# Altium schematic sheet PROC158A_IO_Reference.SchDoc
size A2; Date: Not shown in title block; ApprovedBy: Not shown in title block; CheckedBy: Not shown in title block; Author: Not shown in title block; CompanyName: Not shown in title block; Engineer: Not shown in title block; Organization: Not shown in title block; Address1: Not shown in title block; Address2: Not shown in title block; Address3: Not shown in title block; Address4: Not shown in title block; DocumentNumber: 2; Revision: Use project parameter SCH_Rev; SheetNumber: 2; SheetTotal: 24; PageSetup: Record=PageOptions¦CenterHorizontal=True¦CenterVertical=True¦PrintScale=1.00¦XCorrection=1.00¦YCorrection=1.00¦PrintKind=0¦BorderSize=5000000¦LeftOffset=0¦BottomOffset=0¦Orientation=2¦PaperLength=1000¦PaperWidth=1000¦Scale=100¦PaperSource=15¦PrintQuality=600¦MediaType=1¦DitherType=10¦PaperKind=Letter¦PrintScaleMode=1
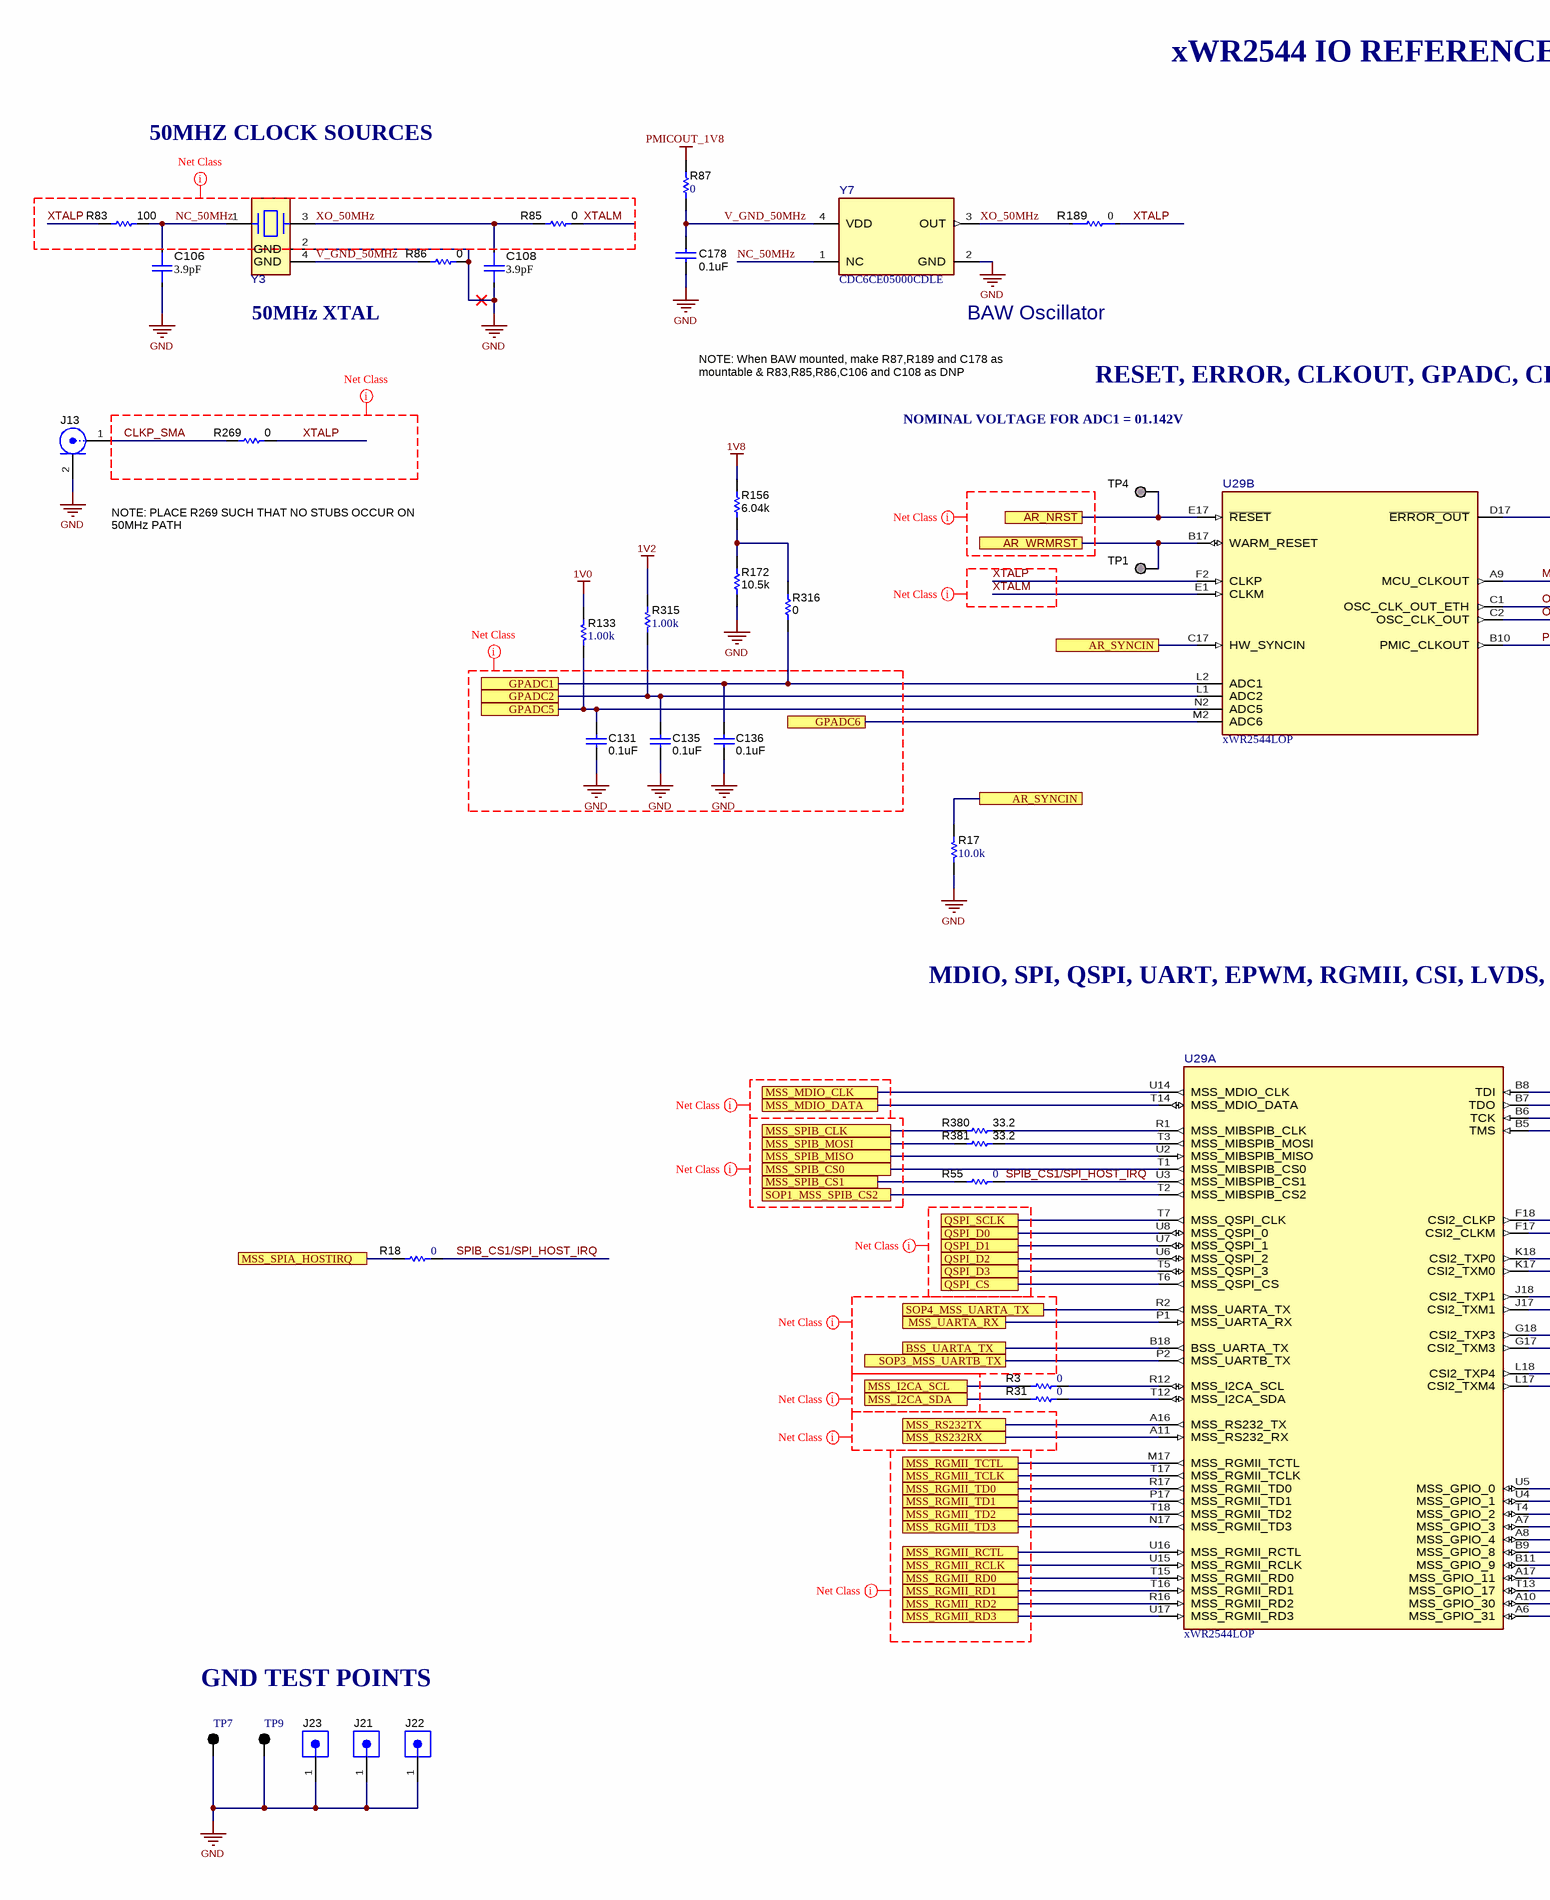
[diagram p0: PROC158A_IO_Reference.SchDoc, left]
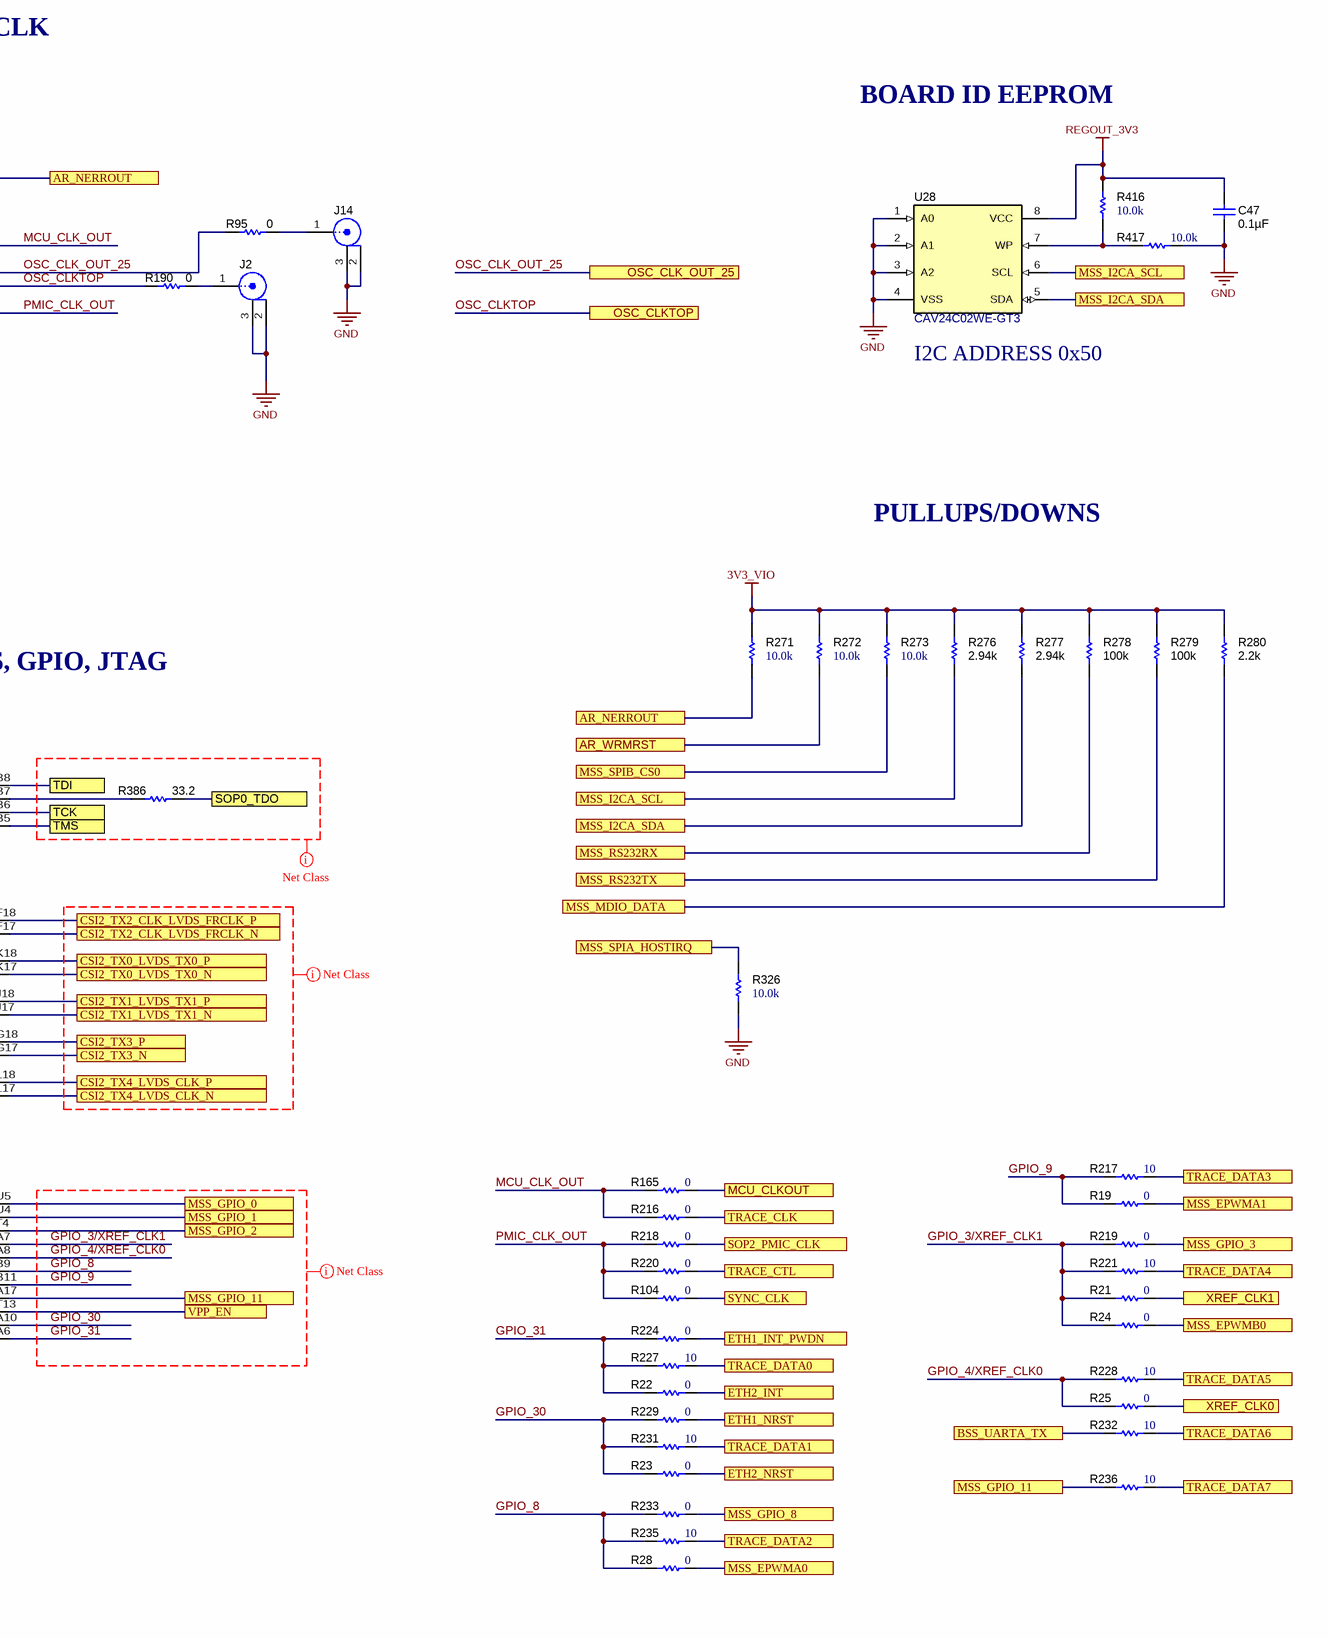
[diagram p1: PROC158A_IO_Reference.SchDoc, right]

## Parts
C47  ValueDisplayed: 0.1µF  [0402L]  (hidden comment: C0402C104K8RACTU)
C106  ValueDisplayed: 3.9pF  [FP-GCM1555C1H3R9BA16D_0402-MFG]  (hidden comment: GCM1555C1H3R9BA16D)
C108  ValueDisplayed: 3.9pF  [FP-GCM1555C1H3R9BA16D_0402-MFG]  (hidden comment: GCM1555C1H3R9BA16D)
C131  ValueDisplayed: 0.1uF  [0402L]  (hidden comment: GCM155R71C104KA55D)
C135  ValueDisplayed: 0.1uF  [0402L]  (hidden comment: GCM155R71C104KA55D)
C136  ValueDisplayed: 0.1uF  [0402L]  (hidden comment: GCM155R71C104KA55D)
C178  ValueDisplayed: 0.1uF  [0402L]  (hidden comment: GCM155R71C104KA55D)
J2  128-0711-201  [Johnson_128-0711-201]  (value not drawn)
J13  142-0711-201  [142-0711-201]  (value not drawn)
J14  128-0711-201  [Johnson_128-0711-201]  (value not drawn)
J21  GBC01SFBN-M30  [Sullins_GBC01SFBN-M30]  (value not drawn)
J22  GBC01SFBN-M30  [Sullins_GBC01SFBN-M30]  (value not drawn)
J23  GBC01SFBN-M30  [Sullins_GBC01SFBN-M30]  (value not drawn)
R3  ValueDisplayed: 0  [0402L]  (hidden comment: ERJ-2GE0R00X)
R17  ValueDisplayed: 10.0k  [0402L]  (hidden comment: CRCW040210K0FKED)
R18  ValueDisplayed: 0  [0201L]  (hidden comment: CRCW02010000Z0ED)
R19  value 0  [0402L]  (hidden comment: ERJ-2GE0R00X)
R21  ValueDisplayed: 0  [0201L]  (hidden comment: CRCW02010000Z0ED)
R22  ValueDisplayed: 0  [0402L]  (hidden comment: ERJ-2GE0R00X)
R23  ValueDisplayed: 0  [0402L]  (hidden comment: ERJ-2GE0R00X)
R24  ValueDisplayed: 0  [0201L]  (hidden comment: CRCW02010000Z0ED)
R25  ValueDisplayed: 0  [0201L]  (hidden comment: CRCW02010000Z0ED)
R28  value 0  [0402L]  (hidden comment: ERJ-2GE0R00X)
R31  ValueDisplayed: 0  [0402L]  (hidden comment: ERJ-2GE0R00X)
R55  ValueDisplayed: 0  [0402L]  (hidden comment: ERJ-2GE0R00X)
R83  ValueDisplayed: 100  [0402L]  (hidden comment: ERJ-2GEJ101X)
R85  ValueDisplayed: 0  [0402L]  (hidden comment: ERJ-2GE0R00X)
R86  ValueDisplayed: 0  [0402L]  (hidden comment: ERJ-2GE0R00X)
R87  ValueDisplayed: 0  [0402L]  (hidden comment: ERJ-2GE0R00X)
R95  ValueDisplayed: 0  [0402L]  (hidden comment: ERJ-2GE0R00X)
R104  ValueDisplayed: 0  [0201L]  (hidden comment: CRCW02010000Z0ED)
R133  ValueDisplayed: 1.00k  [0402L]  (hidden comment: CRCW04021K00FKED)
R156  ValueDisplayed: 6.04k  [0402L]  (hidden comment: CRCW04026K04FKED)
R165  ValueDisplayed: 0  [0201L]  (hidden comment: CRCW02010000Z0ED)
R172  ValueDisplayed: 10.5k  [0402L]  (hidden comment: CRCW040210K5FKED)
R189  Res_ohm: 0  [FP-HCJ0603ZT0R00_0603-MFG]  (hidden comment: HCJ0603ZT0R00)
R190  ValueDisplayed: 0  [0402L]  (hidden comment: ERJ-2GE0R00X)
R216  ValueDisplayed: 0  [0201L]  (hidden comment: CRCW02010000Z0ED)
R217  ValueDisplayed: 10  [0201L]  (hidden comment: RC0201JR-0710RL)
R218  ValueDisplayed: 0  [0201L]  (hidden comment: CRCW02010000Z0ED)
R219  ValueDisplayed: 0  [0201L]  (hidden comment: CRCW02010000Z0ED)
R220  ValueDisplayed: 0  [0201L]  (hidden comment: CRCW02010000Z0ED)
R221  ValueDisplayed: 10  [0201L]  (hidden comment: RC0201JR-0710RL)
R224  ValueDisplayed: 0  [0201L]  (hidden comment: CRCW02010000Z0ED)
R227  ValueDisplayed: 10  [0201L]  (hidden comment: RC0201JR-0710RL)
R228  ValueDisplayed: 10  [0201L]  (hidden comment: RC0201JR-0710RL)
R229  ValueDisplayed: 0  [0201L]  (hidden comment: CRCW02010000Z0ED)
R231  ValueDisplayed: 10  [0201L]  (hidden comment: RC0201JR-0710RL)
R232  ValueDisplayed: 10  [0201L]  (hidden comment: RC0201JR-0710RL)
R233  value 0  [0402L]  (hidden comment: ERJ-2GE0R00X)
R235  ValueDisplayed: 10  [0201L]  (hidden comment: RC0201JR-0710RL)
R236  ValueDisplayed: 10  [0201L]  (hidden comment: RC0201JR-0710RL)
R269  ValueDisplayed: 0  [0402L]  (hidden comment: ERJ-2GE0R00X)
R271  ValueDisplayed: 10.0k  [0402L]  (hidden comment: CRCW040210K0FKED)
R272  ValueDisplayed: 10.0k  [0402L]  (hidden comment: CRCW040210K0FKED)
R273  ValueDisplayed: 10.0k  [0402L]  (hidden comment: CRCW040210K0FKED)
R276  ValueDisplayed: 2.94k  [0402L]  (hidden comment: CRCW04022K94FKED)
R277  ValueDisplayed: 2.94k  [0402L]  (hidden comment: CRCW04022K94FKED)
R278  ValueDisplayed: 100k  [0402L]  (hidden comment: CRCW0402100KFKED)
R279  ValueDisplayed: 100k  [0402L]  (hidden comment: CRCW0402100KFKED)
R280  ValueDisplayed: 2.2k  [0402L]  (hidden comment: CRCW04022K20JNED)
R315  ValueDisplayed: 1.00k  [0402L]  (hidden comment: CRCW04021K00FKED)
R316  ValueDisplayed: 0  [0402L]  (hidden comment: ERJ-2GE0R00X)
R326  ValueDisplayed: 10.0k  [0402L]  (hidden comment: CRCW040210K0FKED)
R380  ValueDisplayed: 33.2  [0402L]  (hidden comment: CRCW040233R2FKED)
R381  ValueDisplayed: 33.2  [0402L]  (hidden comment: CRCW040233R2FKED)
R386  ValueDisplayed: 33.2  [0402L]  (hidden comment: CRCW040233R2FKED)
R416  ValueDisplayed: 10.0k  [0402L]  (hidden comment: CRCW040210K0FKED)
R417  ValueDisplayed: 10.0k  [0402L]  (hidden comment: CRCW040210K0FKED)
TP1  TESTPOINT  [TP_25MIL-SMT]  (value not drawn)  (no BOM)
TP4  TESTPOINT  [TP_25MIL-SMT]  (value not drawn)  (no BOM)
TP7  5001  [Keystone5001]  (value not drawn)
TP9  5001  [Keystone5001]  (value not drawn)
U28  CAV24C02WE-GT3  [SOIC-8]
U29  xWR2544LOP  [0-IPC_C]  (parts A,B of 6)
Y3  NX2016SA-50M-STD-CZS-3  [FP-NX2016SA-50M-STD-CZS-3_SMT4_2MM0_1MM6-MFG]  (value not drawn)
Y7  CDC6CE05000CDLE  [DLE0004A-MFG]

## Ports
AR_NERROUT, AR_NRST, AR_SYNCIN, AR_WRMRST, BSS_UARTA_TX, CSI2_TX0_LVDS_TX0_N, CSI2_TX0_LVDS_TX0_P, CSI2_TX1_LVDS_TX1_N, CSI2_TX1_LVDS_TX1_P, CSI2_TX2_CLK_LVDS_FRCLK_N, CSI2_TX2_CLK_LVDS_FRCLK_P, CSI2_TX3_N, CSI2_TX3_P, CSI2_TX4_LVDS_CLK_N, CSI2_TX4_LVDS_CLK_P, ETH1_INT_PWDN, ETH1_NRST, ETH2_INT, ETH2_NRST, GPADC1, GPADC2, GPADC5, GPADC6, MCU_CLKOUT, MSS_EPWMA0, MSS_EPWMA1, MSS_EPWMB0, MSS_GPIO_0, MSS_GPIO_1, MSS_GPIO_2, MSS_GPIO_3, MSS_GPIO_8, MSS_GPIO_11, MSS_I2CA_SCL, MSS_I2CA_SDA, MSS_MDIO_CLK, MSS_MDIO_DATA, MSS_RGMII_RCLK, MSS_RGMII_RCTL, MSS_RGMII_RD0, MSS_RGMII_RD1, MSS_RGMII_RD2, MSS_RGMII_RD3, MSS_RGMII_TCLK, MSS_RGMII_TCTL, MSS_RGMII_TD0, MSS_RGMII_TD1, MSS_RGMII_TD2, MSS_RGMII_TD3, MSS_RS232RX, MSS_RS232TX, MSS_SPIA_HOSTIRQ, MSS_SPIB_CLK, MSS_SPIB_CS0, MSS_SPIB_CS1, MSS_SPIB_MISO, MSS_SPIB_MOSI, MSS_UARTA_RX, OSC_CLK_OUT_25, OSC_CLKTOP, QSPI_CS, QSPI_D0, QSPI_D1, QSPI_D2, QSPI_D3, QSPI_SCLK, SOP0_TDO, SOP1_MSS_SPIB_CS2, SOP2_PMIC_CLK, SOP3_MSS_UARTB_TX, SOP4_MSS_UARTA_TX, SYNC_CLK, TCK, TDI, TMS, TRACE_CLK, TRACE_CTL, TRACE_DATA0, TRACE_DATA1, TRACE_DATA2, TRACE_DATA3, TRACE_DATA4, TRACE_DATA5, TRACE_DATA6, TRACE_DATA7, VPP_EN, XREF_CLK0, XREF_CLK1

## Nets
1V0: R133.2
1V2: R315.2
1V8: R156.2
3V3_VIO: R271.2 R272.2 R273.2 R276.2 R277.2 R278.2 R279.2 R280.2
GND: C47.1 C106.2 C108.2 C131.1 C135.1 C136.1 C178.1 J2.2 J2.3 J13.2 J14.2 J14.3 J21.1 J22.1 J23.1 R17.1 R86.1 R172.1 R326.1 R417.1 TP7.1 TP9.1 U28.1(A0) U28.2(A1) U28.3(A2) U28.4(VSS) Y3.2(GND) Y7.2(GND)
PMICOUT_1V8: R87.1
REGOUT_3V3: C47.2 R416.2 U28.8(VCC)
AR_NERROUT: R271.1 U29.D17(~{ERROR_OUT}) ; port AR_NERROUT
AR_NRST: TP4.1 U29.E17(~{RESET}) ; port AR_NRST
AR_SYNCIN: R17.2 U29.C17(HW_SYNCIN) ; port AR_SYNCIN
AR_WRMRST: R272.1 TP1.1 U29.B17(WARM_RESET) ; port AR_WRMRST
BSS_UARTA_TX: R232.2 U29.B18(BSS_UARTA_TX) ; port BSS_UARTA_TX
CLKP_SMA: J13.1 R269.2
CSI2_TX0_LVDS_TX0_N: U29.K17(CSI2_TXM0) ; port CSI2_TX0_LVDS_TX0_N
CSI2_TX0_LVDS_TX0_P: U29.K18(CSI2_TXP0) ; port CSI2_TX0_LVDS_TX0_P
CSI2_TX1_LVDS_TX1_N: U29.J17(CSI2_TXM1) ; port CSI2_TX1_LVDS_TX1_N
CSI2_TX1_LVDS_TX1_P: U29.J18(CSI2_TXP1) ; port CSI2_TX1_LVDS_TX1_P
CSI2_TX2_CLK_LVDS_FRCLK_N: U29.F17(CSI2_CLKM) ; port CSI2_TX2_CLK_LVDS_FRCLK_N
CSI2_TX2_CLK_LVDS_FRCLK_P: U29.F18(CSI2_CLKP) ; port CSI2_TX2_CLK_LVDS_FRCLK_P
CSI2_TX3_N: U29.G17(CSI2_TXM3) ; port CSI2_TX3_N
CSI2_TX3_P: U29.G18(CSI2_TXP3) ; port CSI2_TX3_P
CSI2_TX4_LVDS_CLK_N: U29.L17(CSI2_TXM4) ; port CSI2_TX4_LVDS_CLK_N
CSI2_TX4_LVDS_CLK_P: U29.L18(CSI2_TXP4) ; port CSI2_TX4_LVDS_CLK_P
ETH1_INT_PWDN: R224.2 ; port ETH1_INT_PWDN
ETH1_NRST: R229.2 ; port ETH1_NRST
ETH2_INT: R22.1 ; port ETH2_INT
ETH2_NRST: R23.1 ; port ETH2_NRST
GPADC1: C136.2 R316.1 U29.L2(ADC1) ; port GPADC1
GPADC2: C135.2 R315.1 U29.L1(ADC2) ; port GPADC2
GPADC5: C131.2 R133.1 U29.N2(ADC5) ; port GPADC5
GPADC6: U29.M2(ADC6) ; port GPADC6
GPIO_3/XREF_CLK1: R21.1 R24.1 R219.1 R221.2 U29.A7(MSS_GPIO_3)
GPIO_4/XREF_CLK0: R25.1 R228.2 U29.A8(MSS_GPIO_4)
GPIO_8: R28.1 R233.1 R235.2 U29.B9(MSS_GPIO_8)
GPIO_9: R19.1 R217.2 U29.B11(MSS_GPIO_9)
GPIO_30: R23.2 R229.1 R231.2 U29.A10(MSS_GPIO_30)
GPIO_31: R22.2 R224.1 R227.2 U29.A6(MSS_GPIO_31)
MCU_CLK_OUT: R165.1 R216.1 U29.A9(MCU_CLKOUT)
MCU_CLKOUT: R165.2 ; port MCU_CLKOUT
MSS_EPWMA0: R28.2 ; port MSS_EPWMA0
MSS_EPWMA1: R19.2 ; port MSS_EPWMA1
MSS_EPWMB0: R24.2 ; port MSS_EPWMB0
MSS_GPIO_0: U29.U5(MSS_GPIO_0) ; port MSS_GPIO_0
MSS_GPIO_1: U29.U4(MSS_GPIO_1) ; port MSS_GPIO_1
MSS_GPIO_2: U29.T4(MSS_GPIO_2) ; port MSS_GPIO_2
MSS_GPIO_3: R219.2 ; port MSS_GPIO_3
MSS_GPIO_8: R233.2 ; port MSS_GPIO_8
MSS_GPIO_11: R236.2 U29.A17(MSS_GPIO_11) ; port MSS_GPIO_11
MSS_I2CA_SCL: R3.1 R276.1 U28.6(SCL) ; port MSS_I2CA_SCL
MSS_I2CA_SDA: R31.1 R277.1 U28.5(SDA) ; port MSS_I2CA_SDA
MSS_MDIO_CLK: U29.U14(MSS_MDIO_CLK) ; port MSS_MDIO_CLK
MSS_MDIO_DATA: R280.1 U29.T14(MSS_MDIO_DATA) ; port MSS_MDIO_DATA
MSS_RGMII_RCLK: U29.U15(MSS_RGMII_RCLK) ; port MSS_RGMII_RCLK
MSS_RGMII_RCTL: U29.U16(MSS_RGMII_RCTL) ; port MSS_RGMII_RCTL
MSS_RGMII_RD0: U29.T15(MSS_RGMII_RD0) ; port MSS_RGMII_RD0
MSS_RGMII_RD1: U29.T16(MSS_RGMII_RD1) ; port MSS_RGMII_RD1
MSS_RGMII_RD2: U29.R16(MSS_RGMII_RD2) ; port MSS_RGMII_RD2
MSS_RGMII_RD3: U29.U17(MSS_RGMII_RD3) ; port MSS_RGMII_RD3
MSS_RGMII_TCLK: U29.T17(MSS_RGMII_TCLK) ; port MSS_RGMII_TCLK
MSS_RGMII_TCTL: U29.M17(MSS_RGMII_TCTL) ; port MSS_RGMII_TCTL
MSS_RGMII_TD0: U29.R17(MSS_RGMII_TD0) ; port MSS_RGMII_TD0
MSS_RGMII_TD1: U29.P17(MSS_RGMII_TD1) ; port MSS_RGMII_TD1
MSS_RGMII_TD2: U29.T18(MSS_RGMII_TD2) ; port MSS_RGMII_TD2
MSS_RGMII_TD3: U29.N17(MSS_RGMII_TD3) ; port MSS_RGMII_TD3
MSS_RS232RX: R278.1 U29.A11(MSS_RS232_RX) ; port MSS_RS232RX
MSS_RS232TX: R279.1 U29.A16(MSS_RS232_TX) ; port MSS_RS232TX
MSS_SPIA_HOSTIRQ: R18.1 R326.2 ; port MSS_SPIA_HOSTIRQ
MSS_SPIB_CLK: R380.1 ; port MSS_SPIB_CLK
MSS_SPIB_CS0: R273.1 U29.T1(MSS_MIBSPIB_CS0) ; port MSS_SPIB_CS0
MSS_SPIB_CS1: R55.1 ; port MSS_SPIB_CS1
MSS_SPIB_MISO: U29.U2(MSS_MIBSPIB_MISO) ; port MSS_SPIB_MISO
MSS_SPIB_MOSI: R381.1 ; port MSS_SPIB_MOSI
MSS_UARTA_RX: U29.P1(MSS_UARTA_RX) ; port MSS_UARTA_RX
NC_50MHz: C106.1 R83.2 Y3.1(1_XTAL) Y7.1(NC)
OSC_CLK_OUT_25: R95.2 U29.C1(OSC_CLK_OUT_ETH) ; port OSC_CLK_OUT_25
OSC_CLKTOP: R190.2 U29.C2(OSC_CLK_OUT) ; port OSC_CLKTOP
PMIC_CLK_OUT: R104.1 R218.1 R220.1 U29.B10(PMIC_CLKOUT)
QSPI_CS: U29.T6(MSS_QSPI_CS) ; port QSPI_CS
QSPI_D0: U29.U8(MSS_QSPI_0) ; port QSPI_D0
QSPI_D1: U29.U7(MSS_QSPI_1) ; port QSPI_D1
QSPI_D2: U29.U6(MSS_QSPI_2) ; port QSPI_D2
QSPI_D3: U29.T5(MSS_QSPI_3) ; port QSPI_D3
QSPI_SCLK: U29.T7(MSS_QSPI_CLK) ; port QSPI_SCLK
SOP0_TDO: R386.1 ; port SOP0_TDO
SOP1_MSS_SPIB_CS2: U29.T2(MSS_MIBSPIB_CS2) ; port SOP1_MSS_SPIB_CS2
SOP2_PMIC_CLK: R218.2 ; port SOP2_PMIC_CLK
SOP3_MSS_UARTB_TX: U29.P2(MSS_UARTB_TX) ; port SOP3_MSS_UARTB_TX
SOP4_MSS_UARTA_TX: U29.R2(MSS_UARTA_TX) ; port SOP4_MSS_UARTA_TX
SPIB_CS1/SPI_HOST_IRQ: R18.2 R55.2 U29.U3(MSS_MIBSPIB_CS1)
SYNC_CLK: R104.2 ; port SYNC_CLK
TCK: U29.B6(TCK) ; port TCK
TDI: U29.B8(TDI) ; port TDI
TMS: U29.B5(TMS) ; port TMS
TRACE_CLK: R216.2 ; port TRACE_CLK
TRACE_CTL: R220.2 ; port TRACE_CTL
TRACE_DATA0: R227.1 ; port TRACE_DATA0
TRACE_DATA1: R231.1 ; port TRACE_DATA1
TRACE_DATA2: R235.1 ; port TRACE_DATA2
TRACE_DATA3: R217.1 ; port TRACE_DATA3
TRACE_DATA4: R221.1 ; port TRACE_DATA4
TRACE_DATA5: R228.1 ; port TRACE_DATA5
TRACE_DATA6: R232.1 ; port TRACE_DATA6
TRACE_DATA7: R236.1 ; port TRACE_DATA7
V_GND_50MHz: C178.2 R86.2 R87.2 Y3.4(GND) Y7.4(VDD)
VPP_EN: U29.T13(MSS_GPIO_17) ; port VPP_EN
XO_50MHz: C108.1 R85.2 R189.1 Y3.3(2_XTAL) Y7.3(OUT)
XREF_CLK0: R25.2 ; port XREF_CLK0
XREF_CLK1: R21.2 ; port XREF_CLK1
XTALM: R85.1 U29.E1(CLKM)
XTALP: R83.1 R189.2 R269.1 U29.F2(CLKP)
NetJ2_1: J2.1 R190.1
NetJ14_1: J14.1 R95.1
NetR3_2: R3.2 U29.R12(MSS_I2CA_SCL)
NetR31_2: R31.2 U29.T12(MSS_I2CA_SDA)
NetR156_1: R156.1 R172.2 R316.2
NetR380_2: R380.2 U29.R1(MSS_MIBSPIB_CLK)
NetR381_2: R381.2 U29.T3(MSS_MIBSPIB_MOSI)
NetR386_2: R386.2 U29.B7(TDO)
NetR416_1: R416.1 R417.2 U28.7(WP)

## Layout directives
net class 40MHz_CLK: CLKP_SMA, NC_50MHz, XO_50MHz, XTALM, XTALP
net class GPADC: GND
net class I2C: (no net found under the mark)
net class MSS_SPIB: (no net found under the mark)
net class QSPI: (no net found under the mark)
net class CSI: (no net found under the mark)
net class JTAG: (no net found under the mark)
net class GPIO: GPIO_3/XREF_CLK1, GPIO_4/XREF_CLK0, GPIO_8, GPIO_9, GPIO_30, GPIO_31
net class RESET: (no net found under the mark)
net class MDIO: (no net found under the mark)
net class UART: (no net found under the mark)
net class RGMII_TX_RX: (no net found under the mark)

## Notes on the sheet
- xWR2544 IO REFERENCE
- 50MHZ CLOCK SOURCES
- (near Y3) 50MHz XTAL
- (near Y7) BAW Oscillator
- NOTE: When BAW mounted, make R87,R189 and C178 as mountable & R83,R85,R86,C106 and C108 as DNP
- RESET, ERROR, CLKOUT, GPADC, CLK
- NOMINAL VOLTAGE FOR ADC1 = 01.142V
- BOARD ID EEPROM
- NOTE: PLACE R269 SUCH THAT NO STUBS OCCUR ON 50MHz PATH
- (near U28) I2C ADDRESS 0x50
- PULLUPS/DOWNS
- MDIO, SPI, QSPI, UART, EPWM, RGMII, CSI, LVDS, GPIO, JTAG
- GND TEST POINTS

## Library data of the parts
C47 = CMP-0078241-1: CAP, CERM, 0.1 µF, 10 V,+/- 10%, X7R, 0402; Manufacturer: Kemet; TaMin_C: -55°C; Polarized: N; SizeAreaWB_mm2: 3; U/M: EA; Value: 0.1uF; TaMax_C: 125°C; SizeZ_mm: 0.6; SizeX_mm: 1; SizeY_mm: 0.5; Cap_Case: 0402; Value2: 10V; Cap_F: 100nF; AEC Category: Q200
C106 C108 = CMP-0048219-1: Ceramic Capacitor for Automotive 3.9pF ±0.1pF 50VDC C0G 0402 Paper T/R; Manufacturer: Murata; AEC Grade: Grade 1; AEC Qualified: Yes; SizeZ_mm: 0.55mm; TempCo: 30ppm/°C; VDC_V: 50V
C131 C135 C136 C178 = CMP-0006351-2: CAP, CERM, 0.1 uF, 16 V, +/- 10%, X7R, 0402; Manufacturer: MuRata; TaMin_C: -55°C; Polarized: N; SizeAreaWB_mm2: 3; Value1: Unknown; U/M: EA; Value: 0.1uF; TaMax_C: 125°C; SizeZ_mm: 0.6; SizeX_mm: 1; SizeY_mm: 0.5; Cap_Case: 0402; Value2: 16V; CompType: Capacitor; Cap_F: 100nF; AEC Category: Q200
J2 J14 = CMP-0055788-1: UMC Straight Jack Receptacle, 50 Ohm, Gold, SMT; Manufacturer: Cinch Connectivity; CNHeader: FALSE; Gender: Female
J13 = CMP-0055823-2: Connector, SMA Jack, Vertical, Gold, SMD; Manufacturer: Cinch Connectivity; Green_REACh: Incomplete; Green_Lifecycle: Not Set; Gender: Female
J21-J23 = CMP-0084373-1: Header, 1x1, Gold, SMT; Manufacturer: Sullins Connector Solutions; Cert_UL: Y; Current_A: 3A; Gender: Male; Row_Count: 1; Shrouded: N
R3 R22 R23 R31 R55 R85-R87 R95 R190 R269 R316 = CMP-0026992-3: RES, 0, 5%, 0.1 W, AEC-Q200 Grade 0, 0402; Manufacturer: Panasonic; Power_W: 100mW; TempCo: 600 ppm/C; Value_Code: 0000; Value: 0; EIA_Code: E24; SizeX_mm: 1; SizeY_mm: 0.5; SizeZ_mm: 0.6; Value2: 0.1W; AEC Qualified: Y; VDC_V: 50V; AEC Category: Q200; SizeAreaWB_mm2: 3
R17 R271-R273 R326 R416 R417 = CMP-0025958-3: RES, 10.0 k, 1%, 0.063 W, AEC-Q200 Grade 0, 0402; Manufacturer: Vishay-Dale; Power_W: 63mW; TempCo: 100 ppm/C; Value_Code: 10k0; Value: 10.0k; EIA_Code: E96; Res_ohm: 10k; SizeX_mm: 1; SizeY_mm: 0.5; SizeZ_mm: 0.6; Value2: 0.063W; CompType: Resistor; AEC Qualified: Y; VDC_V: 50V; AEC Category: Q200; AEC Grade: 0; INSTALLATION: DNP
R18 R21 R24 R25 R104 R165 R216 R218-R220 R224 R229 = CMP-0027008-4: RES, 0, 5%, 0.05 W, 0201; Manufacturer: Vishay-Dale; Power_W: 50mW; TempCo: ppm/C; Value_Code: 0000; Value: 0; EIA_Code: E24; SizeX_mm: 0.6; SizeY_mm: 0.3; SizeZ_mm: 0.26; Value2: 0.05W; SizeArea_mm2: 0.18; AEC Qualified: N; AEC Category: Q200
R19 R28 R233 = CMP-0026992-3: RES, 0, 5%, 0.1 W, AEC-Q200 Grade 0, 0402; Manufacturer: Panasonic; Power_W: 100mW; TempCo: 600 ppm/C; Value_Code: 0000; EIA_Code: E24; SizeX_mm: 1; SizeY_mm: 0.5; SizeZ_mm: 0.6; Value2: 0.1W; AEC Qualified: Y; VDC_V: 50V; AEC Category: Q200; SizeAreaWB_mm2: 3
R83 = CMP-0026993-2: RES, 100, 5%, 0.1 W, AEC-Q200 Grade 0, 0402; Manufacturer: Panasonic; Power_W: 100mW; TempCo: 200 ppm/C; Value_Code: 100R; U/M: EA; Value: 100; EIA_Code: E24; SizeX_mm: 1; SizeY_mm: 0.5; SizeZ_mm: 0.6; Value2: 0.1W; AEC Qualified: Y; AEC Grade: 0; AEC Category: Q200
R133 R315 = CMP-0026071-3: RES, 1.00 k, 1%, 0.063 W, AEC-Q200 Grade 0, 0402; Manufacturer: Vishay-Dale; Power_W: 63mW; TempCo: 100 ppm/C; Value_Code: 1k00; Value: 1.00k; EIA_Code: E96; Res_ohm: 1k; SizeX_mm: 1; SizeY_mm: 0.5; SizeZ_mm: 0.6; Value2: 0.063W; AEC Qualified: Y; VDC_V: 50V; AEC Category: Q200; AEC Grade: 0
R156 = CMP-0026512-2: RES, 6.04 k, 1%, 0.063 W, AEC-Q200 Grade 0, 0402; Manufacturer: Vishay-Dale; Power_W: 63mW; TempCo: 100 ppm/C; Value_Code: 6k04; Value: 6.04k; EIA_Code: E96; SizeX_mm: 1; SizeY_mm: 0.5; SizeZ_mm: 0.6; Value2: 0.063W; AEC Qualified: Y; VDC_V: 50V; AEC Category: Q200; AEC Grade: 0
R172 = CMP-0025960-3: RES, 10.5 k, 1%, 0.063 W, AEC-Q200 Grade 0, 0402; Manufacturer: Vishay-Dale; Power_W: 63mW; TempCo: 100 ppm/C; Value_Code: 10k5; Value: 10.5k; EIA_Code: E96; SizeX_mm: 1; SizeY_mm: 0.5; SizeZ_mm: 0.6; Value2: 0.063W; AEC Qualified: Y; VDC_V: 50V; AEC Category: Q200; AEC Grade: 0
R189 = CMP-0091690-1: RES 0 OHM JUMPER 1/4W 0603; Manufacturer: Stackpole Electronics; Power_W: 250mW; AEC Grade: Grade 0; AEC Qualified: Yes; SizeZ_mm: 0.7mm; Value: 0
R217 R221 R227 R228 R231 R232 R235 R236 = CMP-0027021-3: RES, 10, 5%, 0.05 W, 0201; Manufacturer: Yageo America; Power_W: 50mW; TempCo: 350 ppm/C; Value_Code: 10R0; U/M: EA; Value: 10; EIA_Code: E24; SizeX_mm: 0.6; SizeY_mm: 0.3; SizeZ_mm: 0.26; Value2: 0.05W; SizeArea_mm2: 0.18; AEC Qualified: N; VDC_V: 25V; AEC Category: Q200
R276 R277 = CMP-0026244-2: RES, 2.94 k, 1%, 0.063 W, AEC-Q200 Grade 0, 0402; Manufacturer: Vishay-Dale; Power_W: 63mW; TempCo: 100 ppm/C; Value_Code: 2k94; Value: 2.94k; EIA_Code: E96; SizeX_mm: 1; SizeY_mm: 0.5; SizeZ_mm: 0.6; Value2: 0.063W; AEC Qualified: Y; VDC_V: 50V; AEC Category: Q200; AEC Grade: 0
R278 R279 = CMP-0025950-3: RES, 100 k, 1%, 0.063 W, AEC-Q200 Grade 0, 0402; Manufacturer: Vishay-Dale; Power_W: 63mW; TempCo: 100 ppm/C; Value: 100k; EIA_Code: E96; SizeX_mm: 1; SizeY_mm: 0.5; SizeZ_mm: 0.6; Value2: 0.063W; AEC Qualified: Y; VDC_V: 50V; AEC Category: Q200; AEC Grade: 0
R280 = CMP-0026890-5: RES, 2.2 k, 5%, 0.063 W, AEC-Q200 Grade 0, 0402; Manufacturer: Vishay-Dale; Power_W: 63mW; TempCo: 200 ppm/C; Value_Code: 2k20; Value: 2.2k; EIA_Code: E24; SizeX_mm: 1; SizeY_mm: 0.5; SizeZ_mm: 0.6; Value2: 0.063W; AEC Qualified: Y; VDC_V: 50V; AEC Category: Q200; AEC Grade: 0
R380 R381 R386 = CMP-0026299-2: RES, 33.2, 1%, 0.063 W, AEC-Q200 Grade 0, 0402; Manufacturer: Vishay-Dale; Power_W: 63mW; TempCo: 100 ppm/C; Value_Code: 33R2; Value: 33.2; EIA_Code: E96; SizeX_mm: 1; SizeY_mm: 0.5; SizeZ_mm: 0.6; Value2: 0.063W; AEC Qualified: Y; VDC_V: 50V; AEC Category: Q200; AEC Grade: 0
TP1 TP4 = CMP-0078143-3: TEST POINT.  No entry in BOM.
TP7 TP9 = CMP-0055138-1: Test Point, Miniature, Black, TH; Manufacturer: Keystone; CNHeader: FALSE; Green_Lifecycle: Active; Green_REACh: Passed; ContactFinish: Silver; CT: TRUE
U28 = CMP-0005318-2: 2-Kb, 4-Kb, 8-Kb and 16-Kb I2C CMOS Serial EEPROM, SOIC-8; Manufacturer: ON Semiconductor; SizeAreaWB_mm2: 55.131; SizeZ_mm: 1.75; SizeX_mm: 5.99; SizeY_mm: 4.9; SizeArea_mm2: 29.351
U29 = CMP-0098489-4: Manufacturer: Texas Instruments; SizeZ_mm: 1.234mm; Standoff Height: 0.216mm; AEC Category: Q200; CompType: IC
Y3 = CMP-0001431-1: 50 MHz ±15ppm Crystal 8pF 50 Ohms 4-SMD, No Lead; Manufacturer: NDK; Frequency Stability: 50ppm; Frequency_Fixed: 50MHz; SizeZ_mm: 0.5mm; AEC Qualified: Yes; AEC Grade: Grade 1; Esr: 50
Y7 = CMP-0094615-2: Crystal replacement: Ultra-low Power LVCMOS Oscillator 4-pin, VSON 3.2 x 2.5 x 0.9mm; Manufacturer: Texas Instruments; AEC Qualified: No; Standoff Height: 0mm; Min Supply Voltage: 2.375V; TaMin_C: -40°C; Load Capacitance: 15pF; Frequency Stability: 20ppm; AEC Category: Q200; Frequency_Fixed: 50MHz; CompType: IC; SizeZ_mm: 1mm; Max Supply Voltage: 3.465V; TJmax_C: +135°C; TaMax_C: +105°C; Max Supply Current: 4mA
